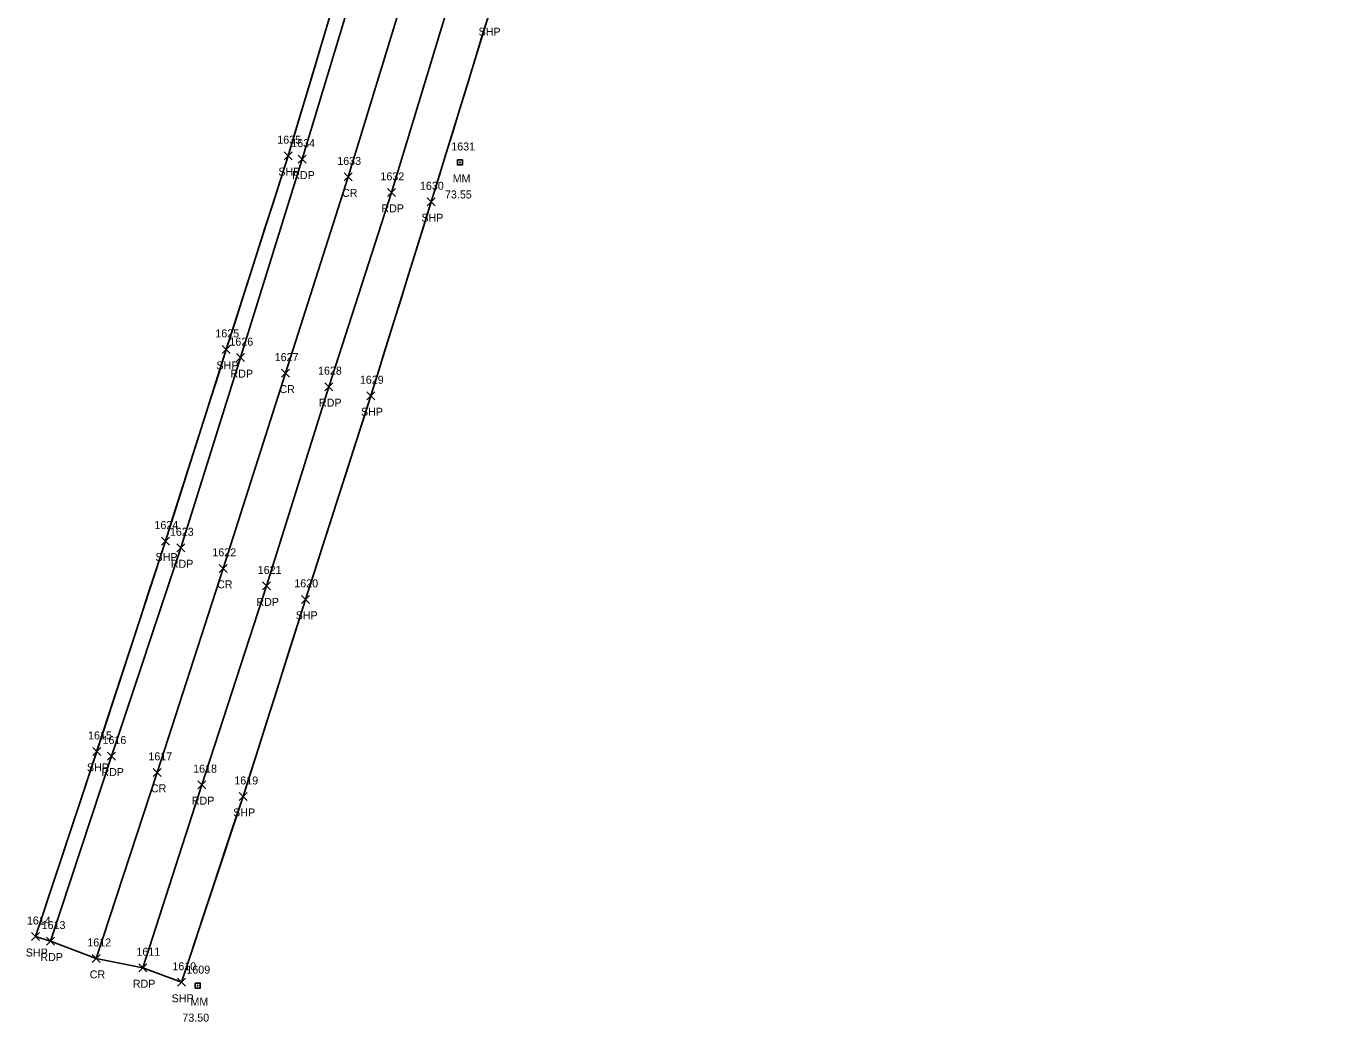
# Model space of a CAD drawing. Extents: x 1688195 to 1692013, y 424605 to 441234.
# Drawn here: x 1690033.3 to 1690361.3, y 433121.6 to 433370.5 of the extents above; entities that cross this region are included whole.
import ezdxf

# ---------------------------------------------------------------- set-up
doc = ezdxf.new("R2010")
doc.units = 0
for name, color, linetype in [('LSOGP', 7, 'Continuous'), ('P_A', 7, 'Continuous'), ('P_I', 7, 'Continuous'), ('P_TIC', 7, 'Continuous'), ('PET', 7, 'Continuous'), ('PRC', 7, 'Continuous'), ('PSP', 7, 'Continuous'), ('S_A', 7, 'Continuous'), ('S_C', 7, 'Continuous'), ('S_I', 7, 'Continuous'), ('SRM', 7, 'Continuous')]:
    doc.layers.add(name, color=color, linetype=linetype)

msp = doc.modelspace()

# ---------------------------------------------------------------- linework, layer by layer
at = {"layer": 'LSOGP'}
msp.add_lwpolyline([(1690108.84, 433371.83), (1690107.16, 433366.21), (1690105.48, 433360.59), (1690103.8, 433354.97), (1690102.12, 433349.35), (1690100.44, 433343.73), (1690098.76, 433338.11), (1690096.82, 433332.05), (1690094.89, 433326), (1690092.95, 433319.95), (1690091.02, 433313.89), (1690089.08, 433307.84), (1690087.15, 433301.79), (1690085.21, 433295.73), (1690083.28, 433289.68), (1690081.38, 433283.69), (1690079.47, 433277.7), (1690077.57, 433271.71), (1690075.67, 433265.72), (1690073.77, 433259.73), (1690071.86, 433253.74), (1690069.96, 433247.75), (1690068.06, 433241.76), (1690065.91, 433235.19), (1690063.77, 433228.62), (1690061.63, 433222.05), (1690059.48, 433215.47), (1690057.34, 433208.9), (1690055.2, 433202.33), (1690047.09, 433177.61), (1690045.18, 433171.83), (1690043.27, 433166.04), (1690041.36, 433160.26), (1690039.45, 433154.47), (1690037.54, 433148.68), (1690035.62, 433142.9), (1690039.31, 433141.76), (1690050.72, 433137.42), (1690062.43, 433135.09), (1690072.07, 433131.46), (1690074, 433137.27), (1690075.92, 433143.07), (1690077.84, 433148.88), (1690079.77, 433154.69), (1690081.69, 433160.49), (1690083.62, 433166.3), (1690085.54, 433172.1), (1690087.47, 433177.91), (1690089.42, 433184.07), (1690091.38, 433190.23), (1690093.33, 433196.39), (1690095.29, 433202.55), (1690097.24, 433208.71), (1690099.2, 433214.87), (1690101.15, 433221.03), (1690103.11, 433227.19), (1690105.15, 433233.55), (1690107.19, 433239.91), (1690109.22, 433246.28), (1690111.26, 433252.64), (1690113.3, 433259), (1690115.34, 433265.37), (1690117.38, 433271.73), (1690119.42, 433278.09), (1690121.31, 433284.15), (1690123.19, 433290.22), (1690125.08, 433296.28), (1690126.96, 433302.34), (1690128.85, 433308.4), (1690130.74, 433314.46), (1690132.62, 433320.53), (1690134.51, 433326.59), (1690136.3, 433332.4), (1690138.08, 433338.22), (1690139.87, 433344.03), (1690141.66, 433349.85), (1690143.45, 433355.66), (1690145.23, 433361.48), (1690147.02, 433367.29), (1690148.81, 433373.11)], dxfattribs=at)
at = {"layer": 'P_TIC'}
for points in [[(1690097.76, 433337.11), (1690099.76, 433339.11)], [(1690099.76, 433337.11), (1690097.76, 433339.11)], [(1690101.26, 433336.25), (1690103.26, 433338.25)], [(1690103.26, 433336.25), (1690101.26, 433338.25)], [(1690112.76, 433331.8), (1690114.76, 433333.8)], [(1690114.76, 433331.8), (1690112.76, 433333.8)], [(1690123.55, 433327.94), (1690125.55, 433329.94)], [(1690125.55, 433327.94), (1690123.55, 433329.94)], [(1690133.51, 433325.59), (1690135.51, 433327.59)], [(1690135.51, 433325.59), (1690133.51, 433327.59)], [(1690082.28, 433288.68), (1690084.28, 433290.68)], [(1690084.28, 433288.68), (1690082.28, 433290.68)], [(1690085.85, 433286.62), (1690087.85, 433288.62)], [(1690087.85, 433286.62), (1690085.85, 433288.62)], [(1690097.12, 433282.75), (1690099.12, 433284.75)], [(1690099.12, 433282.75), (1690097.12, 433284.75)], [(1690107.95, 433279.36), (1690109.95, 433281.36)], [(1690109.95, 433279.36), (1690107.95, 433281.36)], [(1690118.42, 433277.09), (1690120.42, 433279.09)], [(1690120.42, 433277.09), (1690118.42, 433279.09)], [(1690067.06, 433240.76), (1690069.06, 433242.76)], [(1690069.06, 433240.76), (1690067.06, 433242.76)], [(1690070.92, 433239.08), (1690072.92, 433241.08)], [(1690072.92, 433239.08), (1690070.92, 433241.08)], [(1690081.54, 433233.94), (1690083.54, 433235.94)], [(1690083.54, 433233.94), (1690081.54, 433235.94)], [(1690092.3, 433229.54), (1690094.3, 433231.54)], [(1690094.3, 433229.54), (1690092.3, 433231.54)], [(1690102.11, 433226.19), (1690104.11, 433228.19)], [(1690104.11, 433226.19), (1690102.11, 433228.19)], [(1690049.91, 433188.18), (1690051.91, 433190.18)], [(1690051.91, 433188.18), (1690049.91, 433190.18)], [(1690053.57, 433187.01), (1690055.57, 433189.01)], [(1690055.57, 433187.01), (1690053.57, 433189.01)], [(1690065, 433182.94), (1690067, 433184.94)], [(1690067, 433182.94), (1690065, 433184.94)], [(1690076.18, 433179.86), (1690078.18, 433181.86)], [(1690078.18, 433179.86), (1690076.18, 433181.86)], [(1690086.47, 433176.91), (1690088.47, 433178.91)], [(1690088.47, 433176.91), (1690086.47, 433178.91)], [(1690034.62, 433141.9), (1690036.62, 433143.9)], [(1690036.62, 433141.9), (1690034.62, 433143.9)], [(1690038.31, 433140.76), (1690040.31, 433142.76)], [(1690040.31, 433140.76), (1690038.31, 433142.76)], [(1690049.72, 433136.42), (1690051.72, 433138.42)], [(1690051.72, 433136.42), (1690049.72, 433138.42)], [(1690061.43, 433134.09), (1690063.43, 433136.09)], [(1690063.43, 433134.09), (1690061.43, 433136.09)], [(1690071.07, 433130.46), (1690073.07, 433132.46)], [(1690073.07, 433130.46), (1690071.07, 433132.46)]]:
    msp.add_lwpolyline(points, dxfattribs=at)
at = {"layer": 'PET'}
for points in [[(1690039.31, 433141.76), (1690054.57, 433188.01), (1690071.92, 433240.08), (1690086.85, 433287.62), (1690102.26, 433337.25), (1690115.56, 433381.44), (1690131.69, 433432.92), (1690144.59, 433475.99), (1690157.99, 433521.91), (1690171.45, 433568.37), (1690184.55, 433613.87), (1690198.24, 433662.87), (1690210.27, 433706.27), (1690223.3, 433755.05), (1690235.73, 433802.19), (1690247.98, 433848.83), (1690259.12, 433893.75), (1690270.77, 433940.97), (1690282.64, 433988.24), (1690294.48, 434036.45), (1690304.88, 434079.93), (1690315.83, 434126.81), (1690327.01, 434174.5)], [(1690062.43, 433135.09), (1690077.18, 433180.86), (1690093.3, 433230.54), (1690108.95, 433280.36), (1690124.55, 433328.94), (1690138.8, 433375.8), (1690154.11, 433424.03), (1690167.46, 433469.13), (1690181.3, 433514.12), (1690194.42, 433560.22), (1690207.9, 433606.4), (1690221.31, 433654.72), (1690234.27, 433699.14), (1690246.95, 433747.13), (1690259.85, 433795.38), (1690271.49, 433841.23), (1690283.29, 433886.64), (1690294.95, 433934.74), (1690306.71, 433982.08), (1690318.31, 434029.92), (1690329.53, 434076.11), (1690339.32, 434119.7), (1690350.76, 434169.07)]]:
    msp.add_lwpolyline(points, dxfattribs=at)
at = {"layer": 'PRC'}
msp.add_lwpolyline([(1690050.72, 433137.42), (1690066, 433183.94), (1690082.54, 433234.94), (1690098.12, 433283.75), (1690113.76, 433332.8), (1690127.59, 433378.08), (1690142.98, 433428.42), (1690156.2, 433472.69), (1690169.45, 433518.39), (1690182.57, 433564.36), (1690196.15, 433610.32), (1690209.04, 433658.61), (1690222.03, 433703.01), (1690235.13, 433751.31), (1690247.61, 433798.68), (1690259.48, 433845.32), (1690270.53, 433890.06), (1690282.69, 433938.03), (1690294.79, 433985.05), (1690306.25, 434033.34), (1690316.78, 434076.73), (1690327.68, 434123), (1690339.72, 434172)], dxfattribs=at)
at = {"layer": 'PSP'}
for points in [[(1690035.62, 433142.9), (1690050.91, 433189.18), (1690068.06, 433241.76), (1690083.28, 433289.68), (1690098.76, 433338.11), (1690112.2, 433383.07), (1690127.56, 433434.16), (1690141.11, 433477.79), (1690154.03, 433523.19), (1690167.5, 433570.26), (1690180.24, 433615.85), (1690193.97, 433664.12), (1690206.14, 433708.77), (1690219.24, 433756.09), (1690231.62, 433803.9), (1690243.68, 433849.77), (1690255.36, 433895.72), (1690266.7, 433941.79), (1690278.49, 433989.33), (1690289.98, 434036.92), (1690300.41, 434080.72), (1690311.54, 434127.65), (1690322.57, 434175.56)], [(1690072.07, 433131.46), (1690087.47, 433177.91), (1690103.11, 433227.19), (1690119.42, 433278.09), (1690134.51, 433326.59), (1690148.81, 433373.11), (1690163.48, 433420.79), (1690177.06, 433466.35), (1690190.71, 433510.99), (1690203.97, 433557.79), (1690217.09, 433604.48), (1690230.61, 433651.95), (1690243.15, 433696.65), (1690256.23, 433744.76), (1690269.19, 433792.83), (1690281.36, 433839.28), (1690292.85, 433884.41), (1690304.72, 433932.16), (1690316.05, 433979.62), (1690327.5, 434027.37), (1690338.5, 434072.71), (1690349.06, 434117.45), (1690361.33, 434170.48)]]:
    msp.add_lwpolyline(points, dxfattribs=at)
at = {"layer": 'SRM'}
for points in [[(1690141.06, 433337.04), (1690142.31, 433337.04), (1690142.31, 433335.79), (1690141.06, 433335.79)], [(1690075.51, 433131.24), (1690076.76, 433131.24), (1690076.76, 433129.99), (1690075.51, 433129.99)]]:
    msp.add_lwpolyline(points, close=True, dxfattribs=at)
for centre in [(1690141.68, 433336.41), (1690076.13, 433130.62)]:
    msp.add_circle(centre, 0.0833, dxfattribs=at)

# ---------------------------------------------------------------- texts
at = {"layer": 'P_A'}
for s, p in [('SHP', (1690146.34, 433368.11)), ('SHP', (1690096.29, 433333.11)), ('RDP', (1690099.75, 433332.25)), ('CR', (1690112.19, 433327.8)), ('RDP', (1690122.04, 433323.94)), ('SHP', (1690132.04, 433321.59)), ('SHP', (1690080.82, 433284.68)), ('RDP', (1690084.34, 433282.62)), ('CR', (1690096.56, 433278.75)), ('RDP', (1690106.44, 433275.36)), ('SHP', (1690116.95, 433273.09)), ('SHP', (1690065.59, 433236.76)), ('RDP', (1690069.41, 433235.08)), ('CR', (1690080.97, 433229.94)), ('RDP', (1690090.79, 433225.54)), ('SHP', (1690100.64, 433222.19)), ('SHP', (1690048.45, 433184.18)), ('RDP', (1690052.06, 433183.01)), ('CR', (1690064.43, 433178.94)), ('RDP', (1690074.66, 433175.86)), ('SHP', (1690085, 433172.91)), ('SHP', (1690033.16, 433137.9)), ('RDP', (1690036.8, 433136.76)), ('CR', (1690049.15, 433132.42)), ('RDP', (1690059.92, 433130.09)), ('SHP', (1690069.61, 433126.46))]:
    msp.add_text(s, height=2, dxfattribs=at).set_placement(p)
at = {"layer": 'P_I'}
for s, p in [('1635', (1690096.02, 433341.11)), ('1634', (1690099.52, 433340.25)), ('1633', (1690111.02, 433335.8)), ('1632', (1690121.81, 433331.94)), ('1630', (1690131.68, 433329.59)), ('1625', (1690080.54, 433292.68)), ('1626', (1690084.06, 433290.62)), ('1627', (1690095.38, 433286.75)), ('1628', (1690106.21, 433283.36)), ('1629', (1690116.67, 433281.09)), ('1624', (1690065.32, 433244.76)), ('1623', (1690069.18, 433243.08)), ('1622', (1690079.8, 433237.94)), ('1621', (1690091.13, 433233.54)), ('1620', (1690100.28, 433230.19)), ('1615', (1690048.74, 433192.18)), ('1616', (1690052.34, 433191.01)), ('1617', (1690063.82, 433186.94)), ('1618', (1690075, 433183.86)), ('1619', (1690085.29, 433180.91)), ('1614', (1690033.45, 433145.9)), ('1613', (1690037.13, 433144.76)), ('1612', (1690048.54, 433140.42)), ('1611', (1690060.83, 433138.09)), ('1610', (1690069.81, 433134.46))]:
    msp.add_text(s, height=2, dxfattribs=at).set_placement(p)
at = {"layer": 'S_A'}
for p in [(1690139.87, 433331.41), (1690074.32, 433125.62)]:
    msp.add_text('MM', height=2, dxfattribs=at).set_placement(p)
at = {"layer": 'S_C'}
for s, p in [('73.55', (1690137.94, 433327.41)), ('73.50', (1690072.3, 433121.62))]:
    msp.add_text(s, height=2, dxfattribs=at).set_placement(p)
at = {"layer": 'S_I'}
for s, p in [('1631', (1690139.51, 433339.41)), ('1609', (1690073.3, 433133.62))]:
    msp.add_text(s, height=2, dxfattribs=at).set_placement(p)

doc.saveas('drawing.dxf')
